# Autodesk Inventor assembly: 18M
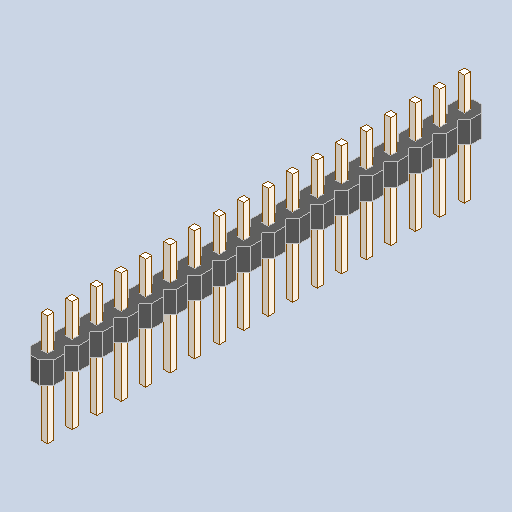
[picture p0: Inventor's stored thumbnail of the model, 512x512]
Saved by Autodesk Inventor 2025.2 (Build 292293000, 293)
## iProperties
Created: 2025-04
Part Number: 18M
Description: PART--DESC
Document SubType Name: Assembly
Designer: BennF
Author: BennF
Revision Number: NONE
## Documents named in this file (3)
- C:\Users\BennF\Nextcloud\Benutzer\CNC JarBeRi\existing parts\Electronics\RepRap A4988 Shied (USE WITHOUT ARDUINO)\reprap-a4988-1.snapshot.1\RepRap\RepRap\18M.iam
- C:\Users\BennF\Nextcloud\Benutzer\CNC JarBeRi\existing parts\Electronics\RepRap A4988 Shied (USE WITHOUT ARDUINO)\reprap-a4988-1.snapshot.1\RepRap\RepRap\18M Geometry.ipt
- C:\Users\BennF\Nextcloud\Benutzer\CNC JarBeRi\existing parts\Electronics\RepRap A4988 Shied (USE WITHOUT ARDUINO)\reprap-a4988-1.snapshot.1\RepRap\RepRap\pin11.ipt
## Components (2 placed, 2 different names)
1. 18M Geometry
2. pin11
